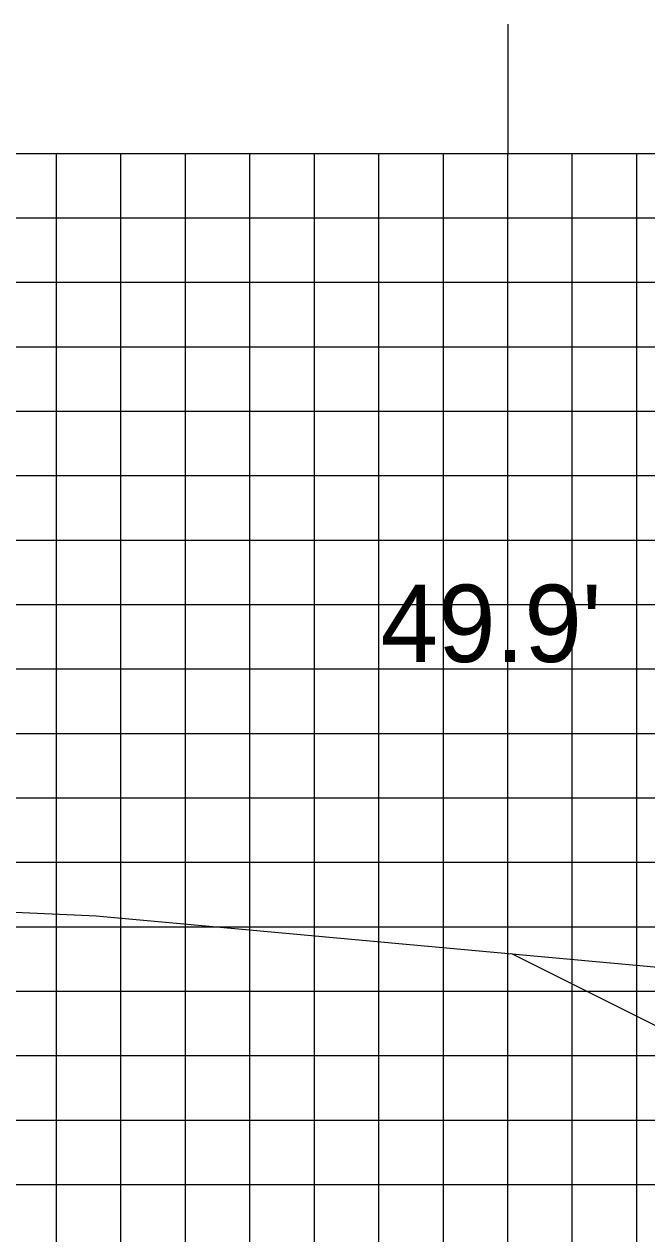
# Model space of a CAD drawing. Extents: x 1772022 to 1772366, y 442591 to 442811.
# Drawn here: x 1772130.59 to 1772140.25, y 442706.9 to 442725.67 of the extents above; entities that cross this region are included whole.
import ezdxf

# ---------------------------------------------------------------- set-up
doc = ezdxf.new("R2010")
doc.units = 0
for name, color, linetype in [('D_Roadway_SlopeLines', 7, 'Continuous'), ('D_Text_Standard', 7, 'Continuous'), ('MAJOR', 7, 'Continuous'), ('MINOR', 7, 'Continuous'), ('S_Roadway_Centerline', 7, 'Continuous')]:
    doc.layers.add(name, color=color, linetype=linetype)

msp = doc.modelspace()

# ---------------------------------------------------------------- linework, layer by layer
at = {"layer": 'D_Roadway_SlopeLines'}
for p, q in [((1772138.603, 442711.02), (1772138.155, 442711.245)), ((1772142.621, 442709.012), (1772138.603, 442711.02))]:
    msp.add_line(p, q, dxfattribs=at)
at = {"layer": 'MAJOR'}
for p, q in [((1772138.094, 442725.669), (1772138.094, 442723.665)), ((1772048.094, 442723.665), (1772328.094, 442723.665)), ((1772048.094, 442723.665), (1772328.094, 442723.665)), ((1772138.094, 442698.665), (1772138.094, 442723.665)), ((1772048.094, 442718.665), (1772328.094, 442718.665)), ((1772048.094, 442713.665), (1772328.094, 442713.665)), ((1772048.094, 442708.665), (1772328.094, 442708.665))]:
    msp.add_line(p, q, dxfattribs=at)
at = {"layer": 'MINOR'}
for p, q in [((1772131.094, 442698.665), (1772131.094, 442723.665)), ((1772132.094, 442698.665), (1772132.094, 442723.665)), ((1772133.094, 442698.665), (1772133.094, 442723.665)), ((1772134.094, 442698.665), (1772134.094, 442723.665)), ((1772135.094, 442698.665), (1772135.094, 442723.665)), ((1772136.094, 442698.665), (1772136.094, 442723.665)), ((1772137.094, 442698.665), (1772137.094, 442723.665)), ((1772139.094, 442698.665), (1772139.094, 442723.665)), ((1772140.094, 442698.665), (1772140.094, 442723.665)), ((1772048.094, 442722.665), (1772328.094, 442722.665)), ((1772048.094, 442721.665), (1772328.094, 442721.665)), ((1772048.094, 442720.665), (1772328.094, 442720.665)), ((1772048.094, 442719.665), (1772328.094, 442719.665)), ((1772048.094, 442717.665), (1772328.094, 442717.665)), ((1772048.094, 442716.665), (1772328.094, 442716.665)), ((1772048.094, 442715.665), (1772328.094, 442715.665)), ((1772048.094, 442714.665), (1772328.094, 442714.665)), ((1772048.094, 442712.665), (1772328.094, 442712.665)), ((1772048.094, 442711.665), (1772328.094, 442711.665)), ((1772048.094, 442710.665), (1772328.094, 442710.665)), ((1772048.094, 442709.665), (1772328.094, 442709.665)), ((1772048.094, 442707.665), (1772328.094, 442707.665))]:
    msp.add_line(p, q, dxfattribs=at)
at = {"layer": 'S_Roadway_Centerline'}
msp.add_lwpolyline([(1772128.852, 442711.962), (1772131.709, 442711.835), (1772148.852, 442710.265), (1772152.553, 442710.074), (1772156.608, 442709.92), (1772164.461, 442710.097), (1772170.743, 442709.418), (1772176.765, 442709.154), (1772184.09, 442709.072), (1772190.39, 442709.167), (1772199.456, 442709.084), (1772211.32, 442708.546), (1772211.609, 442708.541), (1772211.934, 442708.524), (1772231.881, 442708.062), (1772235.01, 442707.943), (1772238.683, 442707.821), (1772252.594, 442707.133)], dxfattribs=at)

# ---------------------------------------------------------------- texts
at = {"layer": 'D_Text_Standard'}
msp.add_text("49.9'", height=1.2, dxfattribs=at).set_placement((1772136.119, 442715.772))

doc.saveas('drawing.dxf')
